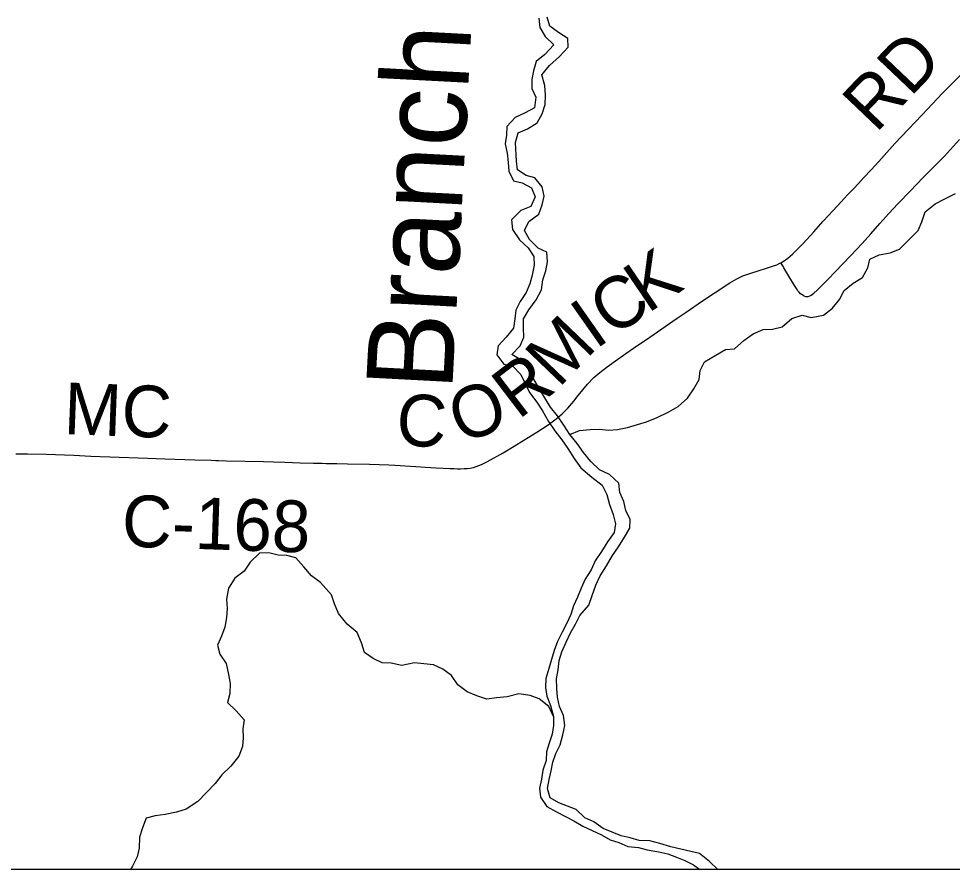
# Model space of a CAD drawing. Extents: x 0 to 34, y 0 to 22.
# Drawn here: x 7.177 to 9.741, y 4.299 to 6.636 of the extents above; entities that cross this region are included whole.
import ezdxf

# ---------------------------------------------------------------- set-up
doc = ezdxf.new("R2010")
doc.units = 0
for name, color, linetype in [('GM_X_County_Road', 7, 'Continuous'), ('GM_X_County_Road_Text', 7, 'Continuous'), ('GM_X_Minor_River', 7, 'Continuous'), ('GM_X_Minor_River_Text', 7, 'Continuous'), ('SH_Text', 7, 'Continuous')]:
    doc.layers.add(name, color=color, linetype=linetype)

msp = doc.modelspace()

# ---------------------------------------------------------------- linework, layer by layer
at = {"layer": 'GM_X_County_Road'}
for points in [[(9.2696, 5.9654), (9.2789, 5.971), (9.2889, 5.978), (9.3017, 5.9889), (9.3311, 6.0185), (9.3603, 6.0505), (9.3861, 6.0797), (9.4136, 6.1093), (9.4354, 6.133), (9.4447, 6.1434), (9.4529, 6.1525), (9.4556, 6.1549), (9.4701, 6.1693), (9.4831, 6.1832), (9.4983, 6.1997), (9.5181, 6.2209), (9.5388, 6.2438), (9.5831, 6.2936), (9.6193, 6.332), (9.658, 6.3718), (9.7141, 6.4311), (9.7743, 6.4916)], [(9.333, 5.8743), (9.3373, 5.8727), (9.3414, 5.8726), (9.3453, 5.8729), (9.3478, 5.8736), (9.3533, 5.8762), (9.3608, 5.8816), (9.3699, 5.89), (9.382, 5.902), (9.4003, 5.9208), (9.4194, 5.941), (9.462, 5.9858), (9.4931, 6.0182), (9.517, 6.0447), (9.5414, 6.0732), (9.5665, 6.1013), (9.5914, 6.1272), (9.6258, 6.163), (9.66, 6.1987), (9.6911, 6.2301), (9.7194, 6.2585), (9.7359, 6.2769), (9.7604, 6.3045)], [(7.1693, 5.4408), (7.1815, 5.4408), (7.2014, 5.4408), (7.2528, 5.4397), (7.329, 5.4367), (7.3753, 5.4345), (7.4271, 5.4321), (7.5305, 5.4284), (7.5786, 5.427), (7.6609, 5.4245), (7.7059, 5.4228), (7.7183, 5.4224), (7.7258, 5.4224), (7.7475, 5.4215), (7.8497, 5.4193), (7.8771, 5.4188), (7.908, 5.4176), (7.9498, 5.4159), (7.9871, 5.415), (8.0103, 5.4145), (8.0211, 5.4144), (8.0505, 5.4138), (8.08, 5.4133), (8.1406, 5.4122), (8.1934, 5.4101), (8.2104, 5.4092), (8.2678, 5.406), (8.2941, 5.4043), (8.3236, 5.4025), (8.3623, 5.4005), (8.3731, 5.3999), (8.3823, 5.3997), (8.3907, 5.3997), (8.4006, 5.4001), (8.4087, 5.4005), (8.417, 5.4016), (8.4256, 5.4031), (8.4335, 5.4058), (8.4478, 5.411), (8.4643, 5.4191), (8.5072, 5.4433), (8.5376, 5.4619), (8.564, 5.4782), (8.5998, 5.5001), (8.631, 5.5203), (8.6534, 5.5368), (8.6698, 5.5508), (8.685, 5.5661), (8.7011, 5.5849), (8.7136, 5.6007), (8.7263, 5.6164), (8.7393, 5.6319), (8.7566, 5.6499), (8.773, 5.6644), (8.7927, 5.6798), (8.8219, 5.7004), (8.8447, 5.7165), (8.865, 5.7309), (8.9099, 5.7615), (8.9856, 5.8131), (9.0097, 5.8302), (9.0546, 5.8609), (9.0897, 5.8839), (9.13, 5.9102), (9.149, 5.9212), (9.166, 5.9293), (9.1821, 5.9355), (9.2133, 5.945), (9.2253, 5.9485), (9.2502, 5.9567), (9.2585, 5.96), (9.2675, 5.9641), (9.2696, 5.9654)], [(9.333, 5.8743), (9.3283, 5.8772), (9.3242, 5.8806), (9.3204, 5.8843), (9.3166, 5.8887), (9.3128, 5.8944), (9.3073, 5.9032), (9.2919, 5.9291), (9.2785, 5.9516), (9.2769, 5.9542), (9.2696, 5.9654)]]:
    msp.add_lwpolyline(points, dxfattribs=at)
at = {"layer": 'GM_X_Minor_River'}
for points in [[(8.8278, 5.334), (8.8247, 5.3596), (8.7998, 5.384), (8.7722, 5.3969), (8.7483, 5.4195), (8.7281, 5.4439), (8.7108, 5.4693), (8.6907, 5.4938), (8.6743, 5.5192), (8.6569, 5.5446), (8.6377, 5.5691), (8.6223, 5.5945), (8.6049, 5.6238), (8.5895, 5.6483), (8.5798, 5.6728), (8.5587, 5.6973), (8.531, 5.7131), (8.5544, 5.7371), (8.5646, 5.7609), (8.5633, 5.7865), (8.5631, 5.8112), (8.5779, 5.8361), (8.5984, 5.8638), (8.6123, 5.8915), (8.6168, 5.9182), (8.625, 5.9429), (8.6295, 5.9677), (8.6273, 5.9942), (8.6035, 6.0053), (8.5795, 6.0297), (8.566, 6.0543), (8.578, 6.0791), (8.6053, 6.0993), (8.6144, 6.1251), (8.6199, 6.1489), (8.6148, 6.1744), (8.5947, 6.1989), (8.5709, 6.2052), (8.5471, 6.2211), (8.544, 6.2448), (8.5415, 6.296), (8.5488, 6.3227), (8.5742, 6.3334), (8.6006, 6.3499), (8.6145, 6.3747), (8.6227, 6.4004), (8.6234, 6.4261), (8.6221, 6.4526), (8.6133, 6.4819), (8.6348, 6.5078), (8.6619, 6.5319), (8.6863, 6.5578), (8.6851, 6.5815), (8.6593, 6.5983), (8.6354, 6.6151), (8.6285, 6.6406)], [(8.6058, 6.6375), (8.608, 6.6119), (8.6225, 6.5874), (8.6464, 6.564), (8.6221, 6.538), (8.5977, 6.5188), (8.5904, 6.4931), (8.586, 6.4693), (8.5862, 6.4446), (8.5969, 6.4201), (8.5935, 6.3915), (8.5681, 6.377), (8.5407, 6.3643), (8.5173, 6.3403), (8.5167, 6.3157), (8.5132, 6.2919), (8.5182, 6.2663), (8.5213, 6.2407), (8.5235, 6.217), (8.5361, 6.1906), (8.5598, 6.1852), (8.5855, 6.1712), (8.5953, 6.1467), (8.5833, 6.1199), (8.5559, 6.1092), (8.5307, 6.0833), (8.5328, 6.0567)], [(8.6907, 5.4938), (8.717, 5.5045), (8.7464, 5.5077), (8.7719, 5.508), (8.7966, 5.5054), (8.8212, 5.5076), (8.8486, 5.5127), (8.8759, 5.5216), (8.9014, 5.5285), (8.9306, 5.5402), (8.9626, 5.5558), (8.988, 5.5703), (9.0133, 5.5934), (9.031, 5.6193), (9.0459, 5.6451), (9.0485, 5.6698), (9.0605, 5.6936), (9.0915, 5.712), (9.1179, 5.7275), (9.1425, 5.7288), (9.1687, 5.7518), (9.1941, 5.7702), (9.2214, 5.7819), (9.247, 5.7831), (9.2734, 5.7891), (9.3006, 5.8122), (9.3289, 5.8211), (9.3536, 5.8148), (9.3867, 5.8218), (9.412, 5.8411), (9.4307, 5.865), (9.4437, 5.8889), (9.469, 5.9091), (9.4944, 5.9246), (9.5092, 5.9514), (9.5147, 5.9752), (9.5401, 5.9869), (9.5703, 5.9929), (9.5958, 6.0027), (9.621, 6.0286), (9.6473, 6.0546), (9.6574, 6.0784), (9.6666, 6.1051), (9.6938, 6.1272), (9.7183, 6.1399), (9.7493, 6.1554)], [(8.5328, 6.0567), (8.5521, 6.0285), (8.576, 6.0069), (8.5914, 5.9824), (8.5926, 5.9587), (8.5873, 5.9311), (8.5809, 5.9073), (8.5708, 5.8834), (8.554, 5.8595), (8.542, 5.8357), (8.5394, 5.8119), (8.5359, 5.7862), (8.5153, 5.7613), (8.4938, 5.7373), (8.4903, 5.7126), (8.5095, 5.6872), (8.5333, 5.6827), (8.5563, 5.6583), (8.5679, 5.6338), (8.5795, 5.6092), (8.5997, 5.5829), (8.6151, 5.5584), (8.6316, 5.5292), (8.6498, 5.5037), (8.669, 5.4793), (8.6854, 5.4548), (8.7028, 5.4275), (8.721, 5.402), (8.7507, 5.3768), (8.7793, 5.3543), (8.7919, 5.3288), (8.7998, 5.3014), (8.8096, 5.274), (8.8155, 5.2484), (8.812, 5.2246), (8.7943, 5.1988), (8.7776, 5.172), (8.7599, 5.1462), (8.7488, 5.1223), (8.733, 5.0965), (8.7219, 5.0717), (8.7118, 5.0469), (8.7007, 5.0231), (8.6934, 4.9992), (8.6823, 4.9754), (8.6693, 4.9505), (8.6563, 4.9248), (8.6471, 4.9), (8.6398, 4.8752), (8.6325, 4.8504), (8.6243, 4.8238), (8.6236, 4.7991), (8.6277, 4.7744), (8.6374, 4.7489), (8.6454, 4.7186), (8.6456, 4.694), (8.6421, 4.6702), (8.6339, 4.6454), (8.6266, 4.6216), (8.6259, 4.5979), (8.6167, 4.5712), (8.6123, 4.5464), (8.6069, 4.5217), (8.61, 4.497), (8.6273, 4.4716), (8.654, 4.4567), (8.7016, 4.4326), (8.7264, 4.4177), (8.7778, 4.3936), (8.8016, 4.3797), (8.8253, 4.3724), (8.8501, 4.3622), (8.8795, 4.3587), (8.9032, 4.3524), (8.9345, 4.3471), (8.9592, 4.3416), (8.983, 4.3324), (9.0067, 4.3232), (9.0305, 4.3111), (9.0476, 4.2991)], [(9.0974, 4.2991), (9.074, 4.3202), (9.0463, 4.3427), (9.0225, 4.3481), (8.9675, 4.3607), (8.938, 4.3699), (8.9105, 4.3771), (8.8811, 4.3787), (8.8564, 4.386), (8.8318, 4.3914), (8.7823, 4.4117), (8.7565, 4.4295), (8.7318, 4.4406), (8.7079, 4.4631), (8.6603, 4.4815), (8.6365, 4.4955), (8.6296, 4.521), (8.634, 4.5457), (8.6395, 4.5695), (8.6439, 4.5933), (8.6522, 4.6171), (8.6642, 4.641), (8.6715, 4.6686), (8.6769, 4.6943), (8.6728, 4.7218), (8.6621, 4.7464), (8.6571, 4.7719), (8.6549, 4.7956), (8.6537, 4.8222), (8.6581, 4.8469), (8.6616, 4.8726), (8.6689, 4.8964), (8.6809, 4.9232), (8.692, 4.9489), (8.706, 4.9728), (8.718, 4.9967), (8.7423, 5.0245), (8.7515, 5.0512), (8.7616, 5.0798), (8.7736, 5.1055), (8.7913, 5.1333), (8.808, 5.161), (8.8238, 5.1849), (8.8406, 5.2117), (8.8554, 5.2366), (8.8561, 5.2603), (8.8445, 5.2848), (8.8385, 5.3094), (8.8278, 5.334)], [(8.6454, 4.7186), (8.6328, 4.746), (8.606, 4.7675), (8.5813, 4.7768), (8.5509, 4.7811), (8.5188, 4.7732), (8.4895, 4.77), (8.463, 4.7668), (8.4355, 4.776), (8.4088, 4.7871), (8.3831, 4.8058), (8.3657, 4.8312), (8.3419, 4.8489), (8.3162, 4.861), (8.2896, 4.8635), (8.264, 4.8661), (8.2291, 4.859), (8.1997, 4.8653), (8.1751, 4.866), (8.1503, 4.878), (8.1264, 4.8948), (8.1186, 4.9213), (8.1069, 4.9497), (8.0792, 4.9731), (8.0552, 5.0022), (8.0445, 5.0287), (8.0357, 5.0533), (8.0059, 5.0871), (7.9811, 5.1058), (7.96, 5.1302), (7.938, 5.1546), (7.9133, 5.161), (7.8896, 5.1626), (7.864, 5.169), (7.8384, 5.1677), (7.8131, 5.1427), (7.7964, 5.1179), (7.771, 5.0986), (7.7533, 5.0718), (7.748, 5.0414), (7.7492, 5.0158), (7.7476, 4.991), (7.7432, 4.9644), (7.734, 4.9396), (7.7229, 4.9148), (7.7298, 4.8902), (7.7471, 4.8648), (7.7531, 4.8345), (7.7581, 4.8099), (7.7566, 4.7823), (7.7502, 4.7576), (7.7741, 4.7341), (7.7962, 4.7097), (7.7927, 4.685), (7.7939, 4.6603), (7.7913, 4.6365), (7.7812, 4.6098), (7.7597, 4.5821), (7.7354, 4.559), (7.7167, 4.535), (7.6933, 4.5101), (7.669, 4.4851), (7.637, 4.4648), (7.6106, 4.456), (7.5794, 4.4499), (7.552, 4.4458), (7.5275, 4.4398), (7.5174, 4.4131), (7.5091, 4.3874), (7.5076, 4.357), (7.5022, 4.3332), (7.4901, 4.3074), (7.4844, 4.2991)]]:
    msp.add_lwpolyline(points, dxfattribs=at)
at = {"layer": 'SH_Text'}
msp.add_lwpolyline([(1.6712, 21.2991), (18.6712, 21.2991), (18.6712, 4.2991), (1.6712, 4.2991)], close=True, dxfattribs=at)

# ---------------------------------------------------------------- texts
at = {"layer": 'GM_X_County_Road_Text'}
for s, height, rotation, p in [('RD', 0.14205, 46.3805, (9.5309, 6.3194)), ('K', 0.142, 34.1689, (8.9045, 5.8246)), ('C', 0.142, 34.2508, (8.8081, 5.759)), ('I', 0.142, 35.0086, (8.7608, 5.7258)), ('M', 0.142, 46.1898, (8.6596, 5.6193)), ('R', 0.142, 37.3717, (8.5491, 5.5326)), ('MC', 0.14205, 357.8134, (7.2993, 5.495)), ('O', 0.142, 20.1469, (8.391, 5.4672)), ('C', 0.142, 356.2231, (8.2109, 5.4657)), ('C-168', 0.14205, 358.0735, (7.4588, 5.1863))]:
    msp.add_text(s, height=height, rotation=rotation, dxfattribs=at).set_placement(p)
at = {"layer": 'GM_X_Minor_River_Text'}
msp.add_text('Branch', height=0.23683, rotation=86.9762, dxfattribs=at).set_placement((8.3674, 5.6119))

doc.saveas('drawing.dxf')
